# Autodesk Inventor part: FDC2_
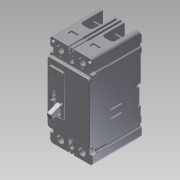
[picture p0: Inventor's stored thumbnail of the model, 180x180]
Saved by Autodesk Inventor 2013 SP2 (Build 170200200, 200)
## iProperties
Created: 2014-08
Part Number: FDC2_
Material: Generic
Document SubType Name: Modeling
Designer: DM/JS
Density: 1 g/cm^3
Description: TYPE FDC THERMAL MAGNETIC CIRCUIT BREAKERS TWO POLE, SERIES C
Translation Standard: STEP AP214IS
FileName: Y:\ECO-062745\WIP\New\FD2_.stp
PreProcessor: Autodesk Inventor 2012
PostProcessor: Build: 219, Release: 2012 SP2 - Date: Fri 04/27/2012
Sent Units: inch
Uncertainty: 0.00039370078740199997
MXEDIT: false
MXINVTNRV: INV Versioned Component|FDC2_|003.0
Author: DM/JS
Revision Number: 003
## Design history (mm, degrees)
node "FDC2_"
node "L1"
node "L2"
node "T1"
node "T2"
body "Solid1"
node "Base1"
